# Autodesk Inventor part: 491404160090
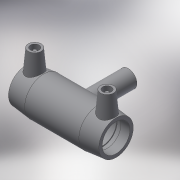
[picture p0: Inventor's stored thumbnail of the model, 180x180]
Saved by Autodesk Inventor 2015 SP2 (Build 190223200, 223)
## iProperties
Created: 2017-06
Part Number: 491404160090
Material: Generic
Description: PLASSON REDUCING TEE 160x90x160
Document SubType Name: Modeling
Designer: KIM
Mass: 57.3761 g
Surface Area: 241.06 cm^2
Volume: 57.3761 cm^3
Density: 1 g/cm^3
Appearance: Default
Author: KIM
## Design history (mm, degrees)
derived "491404.ipt"
feature "Solid1::491404.ipt"
tag "TaggingFeature1"
body "Solid1"
other parameters: "d2" = 208, "d3" = 86, "d4" = 88, "d5" = 187.2, "d6" = 152, "d8" = 168 deg, "d10" = 34.4, "d11" = 11.46667, "d14" = 17.6296, "d17" = 144, "d19" = 3.52592, "d20" = 168 deg, "d22" = 193.44, "d23" = 208, "d25" = 135 deg, "d26" = 308, "d29" = 106, "d30" = 15, "d31" = 176, "d34" = 5 deg, "d35" = 15, "d39" = 5 deg, "d41" = 4, "d42" = 14, "d43" = 0, "d45" = 4, "d46" = 6, "d47" = 0, "d51" = 0, "d52" = 72, "d54" = 0, "d55" = 187.2, "d56" = 208, "d57" = 154, "d58" = 135 deg, "d59" = 86, "d60" = 86, "d61" = 135 deg, "d72" = 200.2, "d73" = 100.1, "d75" = 94.5, "d77" = 0, "d78" = 72, "d80" = 0, "d82" = 76, "d83" = 0, "d84" = 3, "d85" = 0, "d86" = 28.66667, "d87" = 189.5712, "d88" = 11.46667, "d89" = 3, "d90" = 0, "L_1" = 86, "D_" = 208, "A_" = 106, "d_2" = 12
